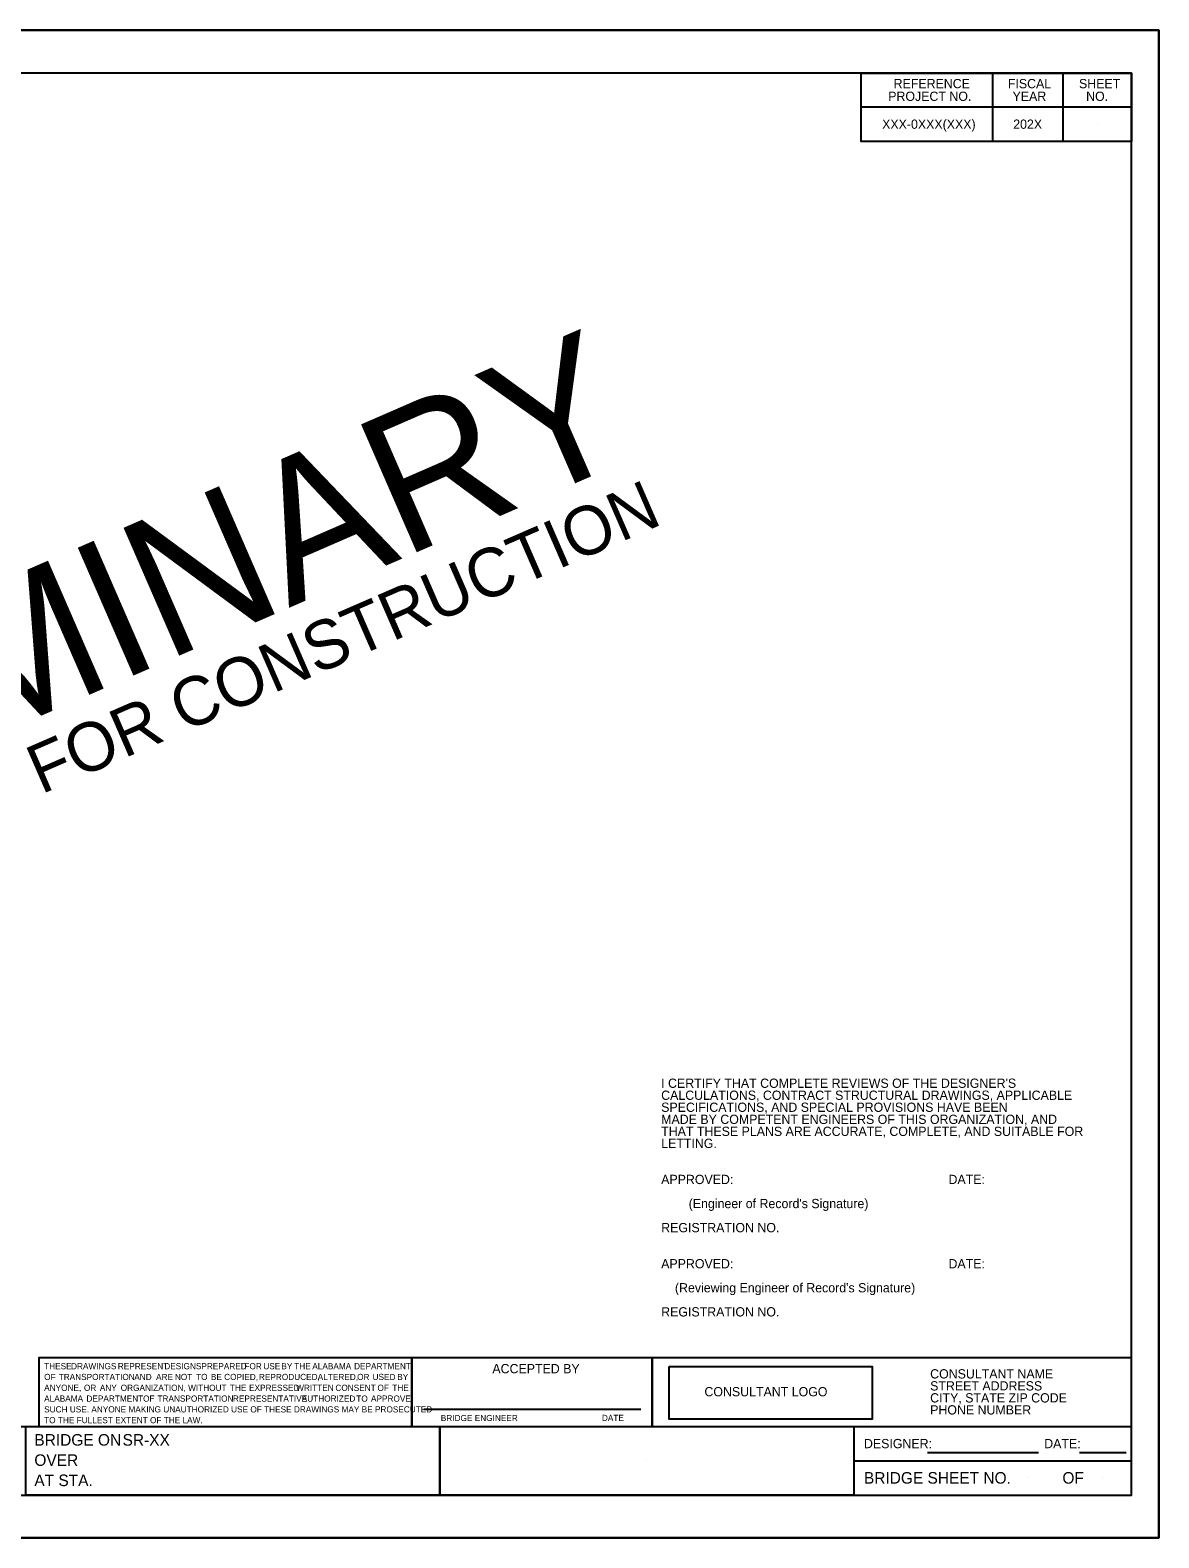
# Model space of a CAD drawing. Extents: x 0 to 2.83, y 0 to 1.83.
# Drawn here: x 1.461 to 2.833, y 0 to 1.833 of the extents above; entities that cross this region are included whole.
import ezdxf

# ---------------------------------------------------------------- set-up
doc = ezdxf.new("R2010")
doc.units = 0
for name, color, linetype in [('Border', 7, 'Continuous'), ('Preliminary', 7, 'Continuous'), ('Project Info', 7, 'Continuous'), ('Reference Points', 7, 'Continuous'), ('SHT-FENCE', 7, 'Continuous'), ('Signatures Box', 7, 'Continuous')]:
    doc.layers.add(name, color=color, linetype=linetype)

msp = doc.modelspace()

# ---------------------------------------------------------------- linework, layer by layer
at = {"layer": 'Border'}
for p, q in [((2.6309, 1.7812), (2.6309, 1.698)), ((2.7166, 1.7812), (2.7166, 1.698)), ((2.4712, 1.7401), (2.8, 1.7401)), ((0.125, 0.1354), (2.8, 0.1354)), ((2.2108, 0.0937), (2.2108, 0.0937)), ((2.4625, 0.0937), (2.8, 0.0937)), ((2.687, 0.1033), (2.552, 0.1033)), ((2.7936, 0.1033), (2.737, 0.1033))]:
    msp.add_line(p, q, dxfattribs=at)
for points in [[(0, 0), (2.8333, 0), (2.8333, 1.8333), (0, 1.8333)], [(0.125, 0.9167), (0.125, 0.0521), (2.8, 0.0521), (2.8, 1.7812), (0.125, 1.7812)], [(2.8, 1.698), (2.4712, 1.698), (2.4712, 1.7812), (2.8, 1.7812)], [(2.2171, 0.1354), (2.8, 0.1354), (2.8, 0.2187), (2.2171, 0.2187)], [(2.2377, 0.2084), (2.4848, 0.2084), (2.4848, 0.1442), (2.2377, 0.1442)], [(1.4556, 0.1354), (1.959, 0.1354), (1.959, 0.0521), (1.4556, 0.0521)], [(1.959, 0.1354), (2.4625, 0.1354), (2.4625, 0.0521), (1.959, 0.0521)]]:
    msp.add_lwpolyline(points, close=True, dxfattribs=at)
at = {"layer": 'Reference Points'}
for p, q in [((2.551, 1.719), (2.551, 1.719)), ((2.6738, 1.719), (2.6738, 1.719)), ((2.7583, 1.719), (2.7583, 1.719)), ((1.4658, 0.1192), (1.4658, 0.1192)), ((2.6746, 0.0729), (2.6746, 0.0729)), ((2.7653, 0.0729), (2.7653, 0.0729))]:
    msp.add_line(p, q, dxfattribs=at)
at = {"layer": 'SHT-FENCE'}
msp.add_lwpolyline([(0, 1.8333), (2.8333, 1.8333), (2.8333, 0), (0, 0)], close=True, dxfattribs=at)
at = {"layer": 'Signatures Box'}
msp.add_line((2.2032, 0.1562), (1.9393, 0.1562), dxfattribs=at)
for points in [[(1.4714, 0.1354), (1.925, 0.1354), (1.925, 0.2187), (1.4714, 0.2187)], [(1.925, 0.1354), (2.2171, 0.1354), (2.2171, 0.2187), (1.925, 0.2187)]]:
    msp.add_lwpolyline(points, close=True, dxfattribs=at)

# ---------------------------------------------------------------- texts
at = {"layer": 'Border'}
for s, height, p in [('REFERENCE', 0.01125, (2.5108, 1.7627)), ('FISCAL', 0.01125, (2.6497, 1.7627)), ('SHEET', 0.01125, (2.7362, 1.7627)), ('PROJECT NO.', 0.01125, (2.5042, 1.7473)), ('YEAR', 0.01125, (2.6554, 1.7473)), ('NO.', 0.01125, (2.7449, 1.7473)), ('CONSULTANT NAME', 0.01125, (2.5552, 0.1938)), ('CONSULTANT LOGO', 0.01125, (2.2807, 0.1721)), ('STREET ADDRESS', 0.01125, (2.5552, 0.1792)), ('CITY, STATE ZIP CODE', 0.01125, (2.5552, 0.1646)), ('PHONE NUMBER', 0.01125, (2.5552, 0.15)), ('DESIGNER:', 0.01125, (2.4747, 0.109)), ('DATE:', 0.01125, (2.6939, 0.109)), ('BRIDGE SHEET NO.            OF', 0.014062, (2.4747, 0.0659))]:
    msp.add_text(s, height=height, dxfattribs=at).set_placement(p)
at = {"layer": 'Preliminary'}
for s, height, p in [('PRELIMINARY', 0.169591, (0.7929, 0.7032)), ('NOT TO BE USED FOR CONSTRUCTION', 0.059132, (0.8416, 0.6285))]:
    msp.add_text(s, height=height, rotation=23.5194, dxfattribs=at).set_placement(p)
at = {"layer": 'Project Info'}
for s, height, p in [('XXX-0XXX(XXX)', 0.01125, (2.4968, 1.7134)), ('202X', 0.01125, (2.6562, 1.7134)), ('BRIDGE ON ', 0.01406, (1.4658, 0.1121)), ('SR-XX', 0.01406, (1.5731, 0.1121)), ('OVER ', 0.01406, (1.4658, 0.0875)), ('AT STA. ', 0.01406, (1.4658, 0.0629))]:
    msp.add_text(s, height=height, dxfattribs=at).set_placement(p)
at = {"layer": 'Signatures Box'}
for s, height, p in [("I CERTIFY THAT COMPLETE REVIEWS OF THE DESIGNER'S", 0.01125, (2.2281, 0.5472)), ('CALCULATIONS, CONTRACT STRUCTURAL DRAWINGS, APPLICABLE', 0.01125, (2.2281, 0.5326)), ('SPECIFICATIONS, AND SPECIAL PROVISIONS HAVE BEEN', 0.01125, (2.2281, 0.518)), ('MADE BY COMPETENT ENGINEERS OF THIS ORGANIZATION, AND', 0.01125, (2.2281, 0.5033)), ('THAT THESE PLANS ARE ACCURATE, COMPLETE, AND SUITABLE FOR ', 0.01125, (2.2281, 0.4887)), ('LETTING.  ', 0.01125, (2.2281, 0.4741)), ('APPROVED:', 0.01125, (2.2281, 0.4302)), ('DATE:', 0.01125, (2.5775, 0.4302)), ("        (Engineer of Record's Signature)", 0.01125, (2.2281, 0.4009)), ('REGISTRATION NO.', 0.01125, (2.2281, 0.3716)), ('APPROVED:', 0.01125, (2.2281, 0.3277)), ('DATE:', 0.01125, (2.5775, 0.3277)), ("    (Reviewing Engineer of Record's Signature)", 0.01125, (2.2281, 0.2985)), ('REGISTRATION NO. ', 0.01125, (2.2281, 0.2692)), ('THESE ', 0.0075, (1.4777, 0.205)), ('DRAWINGS ', 0.0075, (1.5104, 0.205)), ('REPRESENT ', 0.0075, (1.5673, 0.205)), ('DESIGNS ', 0.0075, (1.6238, 0.205)), ('PREPARED ', 0.0075, (1.6689, 0.205)), ('FOR ', 0.0075, (1.7212, 0.205)), ('USE ', 0.0075, (1.7443, 0.205)), ('BY ', 0.0075, (1.7662, 0.205)), ('THE ', 0.0075, (1.7818, 0.205)), ('ALABAMA ', 0.0075, (1.8038, 0.205)), ('DEPARTMENT', 0.0075, (1.8546, 0.205)), ('ACCEPTED BY', 0.01125, (2.0228, 0.2001)), ('ANYONE, ', 0.0075, (1.4777, 0.1787)), ('OF ', 0.0075, (1.4777, 0.1919)), ('TRANSPORTATION ', 0.0075, (1.4954, 0.1919)), ('OR ', 0.0075, (1.5261, 0.1787)), ('ANY ', 0.0075, (1.5454, 0.1787)), ('ORGANIZATION, ', 0.0075, (1.5708, 0.1787)), ('AND ', 0.0075, (1.5873, 0.1919)), ('ARE ', 0.0075, (1.6138, 0.1919)), ('NOT ', 0.0075, (1.6367, 0.1919)), ('WITHOUT ', 0.0075, (1.6528, 0.1787)), ('TO ', 0.0075, (1.6625, 0.1919)), ('BE ', 0.0075, (1.6805, 0.1919)), ('COPIED, ', 0.0075, (1.6966, 0.1919)), ('THE ', 0.0075, (1.7036, 0.1787)), ('EXPRESSED ', 0.0075, (1.7269, 0.1787)), ('REPRODUCED, ', 0.0075, (1.7389, 0.1919)), ('WRITTEN ', 0.0075, (1.7842, 0.1787)), ('ALTERED, ', 0.0075, (1.8104, 0.1919)), ('CONSENT ', 0.0075, (1.8319, 0.1787)), ('OR ', 0.0075, (1.8583, 0.1919)), ('USED ', 0.0075, (1.8771, 0.1919)), ('OF ', 0.0075, (1.883, 0.1787)), ('THE', 0.0075, (1.9011, 0.1787)), ('BY', 0.0075, (1.9071, 0.1919)), ('ALABAMA ', 0.0075, (1.4777, 0.1656)), ('DEPARTMENT ', 0.0075, (1.5291, 0.1656)), ('OF ', 0.0075, (1.598, 0.1656)), ('TRANSPORTATION ', 0.0075, (1.6155, 0.1656)), ('REPRESENTATIVE ', 0.0075, (1.7073, 0.1656)), ('AUTHORIZED ', 0.0075, (1.791, 0.1656)), ('TO ', 0.0075, (1.8573, 0.1656)), ('APPROVE', 0.0075, (1.8752, 0.1656)), ('TO THE FULLEST EXTENT OF THE LAW.', 0.0075, (1.4777, 0.1394)), ('SUCH USE. ANYONE MAKING UNAUTHORIZED USE OF THESE DRAWINGS MAY BE PROSECUTED', 0.0075, (1.4777, 0.1525)), ('BRIDGE ENGINEER', 0.0075, (1.9601, 0.142)), ('DATE', 0.0075, (2.156, 0.1421))]:
    msp.add_text(s, height=height, dxfattribs=at).set_placement(p)

doc.saveas('drawing.dxf')
